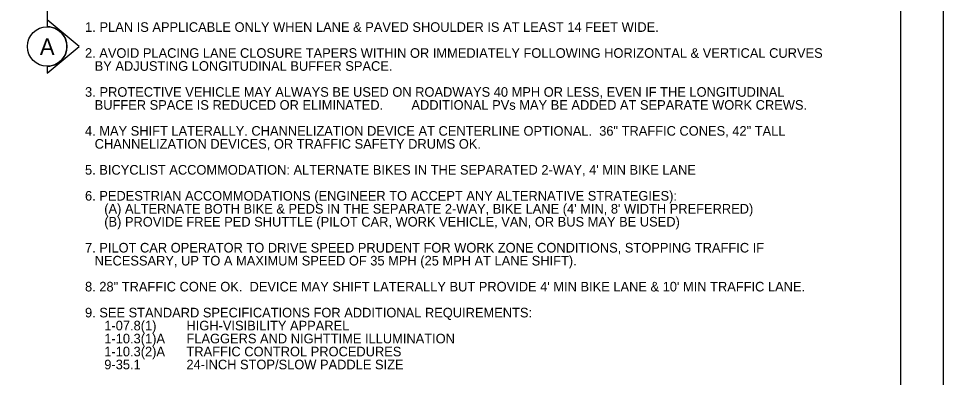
# Model space of a CAD drawing. Extents: x 99999.1 to 100095.7, y 99995 to 100010.7.
# Drawn here: x 100049.33 to 100056.06, y 100002.9 to 100005.51 of the extents above; entities that cross this region are included whole.
import ezdxf

# ---------------------------------------------------------------- set-up
doc = ezdxf.new("R2010")
doc.units = 0
for name, color, linetype in [('SH_GI_GeneralNotesBodyText', 7, 'Continuous'), ('SH_GI_PlotLimits', 7, 'Continuous'), ('SH_GI_SectionCut', 7, 'Continuous'), ('SH_GI_SheetBorder', 7, 'Continuous')]:
    doc.layers.add(name, color=color, linetype=linetype)

msp = doc.modelspace()

# ---------------------------------------------------------------- linework, layer by layer
at = {"layer": 'SH_GI_PlotLimits'}
msp.add_lwpolyline([(100039.0625, 99999.6875), (100056.0625, 99999.6875), (100056.0625, 100010.6875), (100039.0625, 100010.6875)], close=True, dxfattribs=at)
at = {"layer": 'SH_GI_SectionCut'}
for p, q in [((100049.5338, 100007.7396), (100049.5338, 100005.4996)), ((100049.5337, 100005.4996), (100049.5337, 100005.4487)), ((100049.7664, 100005.3048), (100049.5337, 100005.4996)), ((100049.5337, 100005.1099), (100049.7664, 100005.3048)), ((100049.5337, 100005.1608), (100049.5337, 100005.1099))]:
    msp.add_line(p, q, dxfattribs=at)
msp.add_circle((100049.5338, 100005.3048), 0.144, dxfattribs=at)
msp.add_arc((100049.5338, 100005.3048), 0.144, 269.99779, 90.00221, dxfattribs=at)
at = {"layer": 'SH_GI_SheetBorder'}
msp.add_line((100055.75, 100010.375), (100055.75, 100000), dxfattribs=at)

# ---------------------------------------------------------------- texts
at = {"layer": 'SH_GI_GeneralNotesBodyText'}
for s, p in [('1. ', (100049.8098, 100005.4116)), ('PLAN IS APPLICABLE ONLY WHEN LANE & PAVED SHOULDER IS AT LEAST 14 FEET WIDE.', (100049.9155, 100005.4116)), ('2. AVOID PLACING LANE CLOSURE TAPERS WITHIN OR IMMEDIATELY FOLLOWING HORIZONTAL & VERTICAL CURVES ', (100049.8098, 100005.2226)), ('BY ADJUSTING LONGITUDINAL BUFFER SPACE.', (100049.88, 100005.1281)), ('3. ', (100049.8098, 100004.9391)), ('PROTECTIVE VEHICLE MAY ALWAYS BE USED ON ROADWAYS 40 MPH OR LESS, EVEN IF THE LONGITUDINAL ', (100049.9155, 100004.9391)), ('BUFFER SPACE IS REDUCED OR ELIMINATED.', (100049.88, 100004.8446)), ('  ADDITIONAL PVs MAY BE ADDED AT SEPARATE WORK CREWS.', (100052.1353, 100004.8446)), ('4. MAY SHIFT LATERALLY. CHANNELIZATION DEVICE AT CENTERLINE OPTIONAL.  36" TRAFFIC CONES, 42" TALL ', (100049.8098, 100004.6556)), ('CHANNELIZATION DEVICES, OR TRAFFIC SAFETY DRUMS OK.', (100049.88, 100004.5611)), ("5. BICYCLIST ACCOMMODATION: ALTERNATE BIKES IN THE SEPARATED 2-WAY, 4' MIN BIKE LANE", (100049.8098, 100004.3721)), ('6. PEDESTRIAN ACCOMMODATIONS (ENGINEER TO ACCEPT ANY ALTERNATIVE STRATEGIES):', (100049.8098, 100004.1831)), ("(A) ALTERNATE BOTH BIKE & PEDS IN THE SEPARATE 2-WAY, BIKE LANE (4' MIN, 8' WIDTH PREFERRED)", (100049.9498, 100004.0886)), ('(B) PROVIDE FREE PED SHUTTLE (PILOT CAR, WORK VEHICLE, VAN, OR BUS MAY BE USED)', (100049.9498, 100003.9941)), ('7. PILOT CAR OPERATOR TO DRIVE SPEED PRUDENT FOR WORK ZONE CONDITIONS, STOPPING TRAFFIC IF ', (100049.8098, 100003.8051)), ('NECESSARY, UP TO A MAXIMUM SPEED OF 35 MPH (25 MPH AT LANE SHIFT).', (100049.88, 100003.7106)), ('8. 28" TRAFFIC CONE OK.  DEVICE MAY SHIFT LATERALLY BUT PROVIDE 4\' MIN BIKE LANE & 10\' MIN TRAFFIC LANE.', (100049.8098, 100003.5216)), ('9. SEE STANDARD SPECIFICATIONS FOR ADDITIONAL REQUIREMENTS:', (100049.8098, 100003.3326)), ('1-07.8(1) ', (100049.9502, 100003.2381)), ('HIGH-VISIBILITY APPAREL', (100050.5487, 100003.2381)), ('1-10.3(1)A ', (100049.9502, 100003.1436)), ('FLAGGERS AND NIGHTTIME ILLUMINATION', (100050.5487, 100003.1436)), ('1-10.3(2)A', (100049.9502, 100003.0491)), ('TRAFFIC CONTROL PROCEDURES', (100050.5487, 100003.0491)), ('9-35.1', (100049.9502, 100002.9546)), ('24-INCH STOP/SLOW PADDLE SIZE', (100050.5487, 100002.9546))]:
    msp.add_text(s, height=0.07, rotation=360, dxfattribs=at).set_placement(p)
at = {"layer": 'SH_GI_SectionCut'}
msp.add_text('A', height=0.12, rotation=0.00995, dxfattribs=at).set_placement((100049.4809, 100005.2439))

doc.saveas('drawing.dxf')
